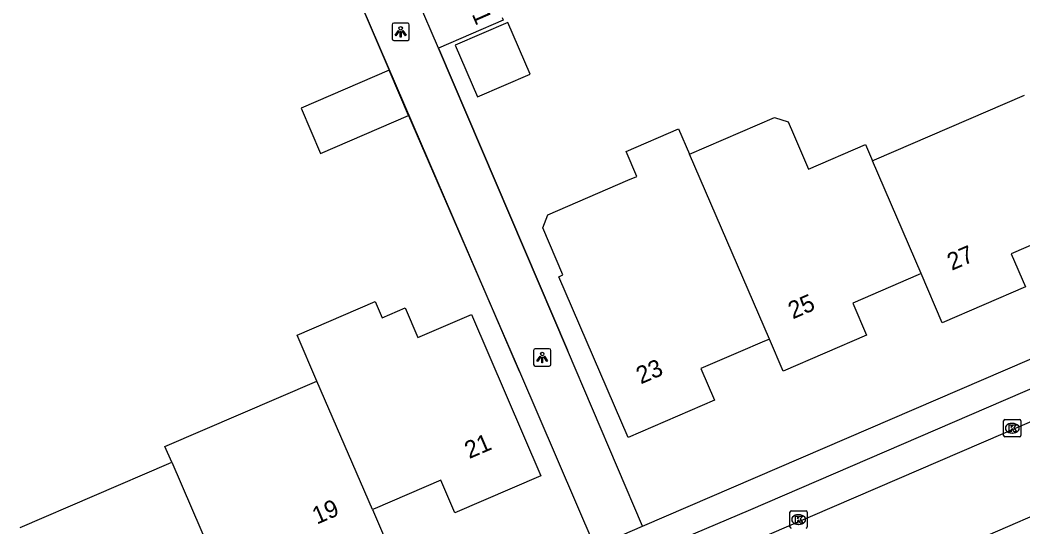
# Model space of a CAD drawing. Extents: x 157767 to 159171, y 387842 to 389425.
# Drawn here: x 158190.7 to 158248.5, y 388683 to 388712.2 of the extents above; entities that cross this region are included whole.
import ezdxf

# ---------------------------------------------------------------- set-up
doc = ezdxf.new("R2010")
doc.units = 0
for name, color, linetype in [('IMGEO_Kolk', 7, 'Continuous'), ('IMGEO_Lichtpunt', 7, 'Continuous'), ('IMGEO_Muur', 7, 'Continuous'), ('IMGEO_Pand', 7, 'Continuous'), ('IMGEO_Pand_nummerreeks', 7, 'Continuous'), ('IMGEO_Rijbaan_lokaal_open', 7, 'Continuous'), ('IMGEO_Voetpad_open', 7, 'Continuous')]:
    doc.layers.add(name, color=color, linetype=linetype)

msp = doc.modelspace()

# ---------------------------------------------------------------- linework, layer by layer
at = {"layer": 'IMGEO_Kolk'}
for p, q in [((158247.391, 388688.278), (158247.391, 388689.13)), ((158247.466, 388689.204), (158248.318, 388689.204)), ((158247.879, 388688.984), (158247.904, 388688.984)), ((158248.392, 388689.13), (158248.392, 388688.278)), ((158248.318, 388688.204), (158247.466, 388688.204)), ((158247.902, 388688.424), (158247.877, 388688.424)), ((158235.076, 388683.017), (158235.076, 388683.869)), ((158235.151, 388683.943), (158236.003, 388683.943)), ((158235.564, 388683.723), (158235.589, 388683.723)), ((158236.077, 388683.869), (158236.077, 388683.017)), ((158235.587, 388683.163), (158235.562, 388683.163))]:
    msp.add_line(p, q, dxfattribs=at)
for points in [[(158247.391, 388688.278), (158247.391, 388689.13)], [(158247.466, 388689.204), (158248.318, 388689.204)], [(158247.712, 388688.904), (158247.835, 388688.904), (158247.835, 388688.753), (158247.965, 388688.904), (158248.129, 388688.904), (158247.983, 388688.753), (158248.136, 388688.504), (158247.984, 388688.504), (158247.899, 388688.668), (158247.835, 388688.601), (158247.835, 388688.504), (158247.712, 388688.504), (158247.712, 388688.904)], [(158248.392, 388689.13), (158248.392, 388688.278)], [(158248.318, 388688.204), (158247.466, 388688.204)], [(158235.076, 388683.017), (158235.076, 388683.869)], [(158235.151, 388683.943), (158236.003, 388683.943)], [(158235.397, 388683.643), (158235.52, 388683.643), (158235.52, 388683.492), (158235.65, 388683.643), (158235.814, 388683.643), (158235.668, 388683.492), (158235.821, 388683.243), (158235.669, 388683.243), (158235.584, 388683.407), (158235.52, 388683.34), (158235.52, 388683.243), (158235.397, 388683.243), (158235.397, 388683.643)], [(158236.077, 388683.869), (158236.077, 388683.017)]]:
    msp.add_lwpolyline(points, dxfattribs=at)
for centre, start, end in [((158247.468, 388689.128), 91.55205, 178.44795), ((158247.468, 388689.128), 91.55205, 178.44795), ((158248.316, 388689.128), 1.55205, 88.44795), ((158248.316, 388689.128), 1.55205, 88.44795), ((158247.468, 388688.28), 181.55205, 268.44795), ((158247.468, 388688.28), 181.55205, 268.44795), ((158248.316, 388688.28), 271.55205, 358.44795), ((158248.316, 388688.28), 271.55205, 358.44795), ((158235.153, 388683.867), 91.55205, 178.44795), ((158235.153, 388683.867), 91.55205, 178.44795), ((158236.001, 388683.867), 1.55205, 88.44795), ((158236.001, 388683.867), 1.55205, 88.44795), ((158235.153, 388683.019), 181.55205, 268.44795), ((158235.153, 388683.019), 181.55205, 268.44795), ((158236.001, 388683.019), 271.55205, 358.44795), ((158236.001, 388683.019), 271.55205, 358.44795)]:
    msp.add_arc(centre, 0.0765, start, end, dxfattribs=at)
for centre, major_axis, ratio, start_param, end_param in [((158247.878, 388688.704), (-0.387, 0.002), 0.722429, 4.712389, 7.853982), ((158247.903, 388688.704), (-0.39, 0.002), 0.717154, 1.570796, 4.712389), ((158235.563, 388683.443), (-0.387, 0.002), 0.722429, 4.712389, 7.853982), ((158235.588, 388683.443), (-0.39, 0.002), 0.717154, 1.570796, 4.712389)]:
    msp.add_ellipse(centre, major_axis=major_axis, ratio=ratio, start_param=start_param, end_param=end_param, dxfattribs=at)
at = {"layer": 'IMGEO_Lichtpunt'}
for p, q in [((158212.142, 388711.942), (158212.142, 388711.135)), ((158212.142, 388711.942), (158212.142, 388711.135)), ((158213.044, 388712.037), (158212.236, 388712.037)), ((158213.044, 388712.037), (158212.236, 388712.037)), ((158213.138, 388711.135), (158213.138, 388711.942)), ((158213.138, 388711.135), (158213.138, 388711.942)), ((158212.236, 388711.041), (158213.044, 388711.041)), ((158212.236, 388711.041), (158213.044, 388711.041)), ((158220.3, 388693.182), (158220.3, 388692.375)), ((158220.3, 388693.182), (158220.3, 388692.375)), ((158221.202, 388693.277), (158220.394, 388693.277)), ((158221.202, 388693.277), (158220.394, 388693.277)), ((158221.296, 388692.375), (158221.296, 388693.182)), ((158221.296, 388692.375), (158221.296, 388693.182)), ((158220.394, 388692.281), (158221.202, 388692.281)), ((158220.394, 388692.281), (158221.202, 388692.281))]:
    msp.add_line(p, q, dxfattribs=at)
for points in [[(158212.516, 388711.606), (158212.555, 388711.578), (158212.367, 388711.316), (158212.329, 388711.343), (158212.516, 388711.606)], [(158212.618, 388711.558), (158212.665, 388711.558), (158212.665, 388711.236), (158212.618, 388711.236), (158212.618, 388711.558)], [(158212.728, 388711.578), (158212.766, 388711.605), (158212.953, 388711.343), (158212.914, 388711.315), (158212.728, 388711.578)], [(158220.674, 388692.846), (158220.713, 388692.818), (158220.525, 388692.556), (158220.487, 388692.583), (158220.674, 388692.846)], [(158220.776, 388692.798), (158220.823, 388692.798), (158220.823, 388692.476), (158220.776, 388692.476), (158220.776, 388692.798)], [(158220.886, 388692.818), (158220.924, 388692.845), (158221.111, 388692.583), (158221.072, 388692.555), (158220.886, 388692.818)]]:
    msp.add_lwpolyline(points, dxfattribs=at)
for centre in [(158212.641, 388711.74), (158220.799, 388692.98)]:
    msp.add_circle(centre, 0.0994, dxfattribs=at)
for centre, start, end in [((158212.236, 388711.942), 90, 180), ((158212.236, 388711.942), 90, 180), ((158213.044, 388711.942), 0, 90), ((158213.044, 388711.942), 0, 90), ((158212.236, 388711.135), 180, 270), ((158212.236, 388711.135), 180, 270), ((158213.044, 388711.135), 270, 0), ((158213.044, 388711.135), 270, 360), ((158220.394, 388693.182), 90, 180), ((158220.394, 388693.182), 90, 180), ((158221.202, 388693.182), 0, 90), ((158221.202, 388693.182), 0, 90), ((158220.394, 388692.375), 180, 270), ((158220.394, 388692.375), 180, 270), ((158221.202, 388692.375), 270, 0), ((158221.202, 388692.375), 270, 360)]:
    msp.add_arc(centre, 0.0946, start, end, dxfattribs=at)
at = {"layer": 'IMGEO_Muur'}
for points in [[(158219.492, 388691.965), (158208.082, 388718.445), (158205.742, 388723.876)], [(158214.816, 388710.595), (158222.246, 388693.191)]]:
    msp.add_lwpolyline(points, dxfattribs=at)
at = {"layer": 'IMGEO_Pand'}
for points in [[(158214.816, 388710.595), (158213.602, 388713.414)], [(158218.48, 388712.357), (158218.547, 388712.202), (158214.816, 388710.595)], [(158215.79, 388710.767), (158217.072, 388707.789), (158220.106, 388709.096), (158218.824, 388712.074), (158215.79, 388710.767)], [(158211.972, 388709.33), (158206.896, 388707.144), (158208.021, 388704.53), (158213.098, 388706.716)], [(158213.098, 388706.716), (158211.972, 388709.33)], [(158239.84, 388704.111), (158239.947, 388704.157), (158248.597, 388707.882)], [(158229.293, 388704.49), (158234.184, 388706.595), (158234.98, 388706.355), (158235.287, 388705.642), (158236.152, 388703.634), (158239.437, 388705.049), (158239.84, 388704.111)], [(158233.895, 388693.842), (158233.481, 388693.663), (158232.221, 388693.121), (158229.942, 388692.139), (158230.729, 388690.311), (158225.746, 388688.165), (158221.755, 388697.433), (158221.994, 388697.536), (158220.824, 388700.255), (158221.123, 388701.005), (158225.725, 388702.986), (158226.249, 388703.211), (158225.629, 388704.652), (158228.644, 388705.95), (158229.293, 388704.49)], [(158233.895, 388693.842), (158229.293, 388704.49)], [(158242.631, 388697.609), (158239.84, 388704.111)], [(158251.79, 388700.46), (158247.825, 388698.752), (158248.644, 388696.85), (158243.844, 388694.783), (158242.631, 388697.609)], [(158242.631, 388697.609), (158242.462, 388697.536), (158238.694, 388695.913), (158239.493, 388694.059), (158234.695, 388691.992), (158233.895, 388693.842)], [(158207.814, 388691.423), (158206.671, 388694.073), (158211.164, 388696.012), (158211.575, 388695.06), (158212.904, 388695.633), (158213.637, 388693.932), (158216.719, 388695.259), (158220.723, 388685.962), (158215.765, 388683.826), (158214.953, 388685.71), (158211.176, 388684.083), (158211.011, 388684.012)], [(158199.444, 388686.74), (158199.051, 388687.649), (158207.814, 388691.423)], [(158211.011, 388684.012), (158207.814, 388691.423)], [(158190.702, 388682.975), (158199.284, 388686.671), (158199.444, 388686.74)], [(158199.444, 388686.74), (158202.255, 388680.24)], [(158211.011, 388684.012), (158211.822, 388682.131), (158206.977, 388680.044), (158206.167, 388681.924), (158202.402, 388680.303), (158202.255, 388680.24)]]:
    msp.add_lwpolyline(points, dxfattribs=at)
at = {"layer": 'IMGEO_Rijbaan_lokaal_open'}
for points in [[(158229.383, 388680.571), (158233.906, 388682.603), (158267.072, 388696.894), (158267.966, 388697.279)], [(158255.291, 388686.339), (158244.298, 388681.584)]]:
    msp.add_lwpolyline(points, dxfattribs=at)
at = {"layer": 'IMGEO_Voetpad_open'}
for points in [[(158208.082, 388718.445), (158211.972, 388709.33)], [(158226.572, 388683.059), (158265.791, 388699.949), (158281.335, 388706.644), (158293.914, 388712.06)], [(158226.572, 388683.059), (158222.246, 388693.191), (158214.816, 388710.595)], [(158291.521, 388707.835), (158291.008, 388709.09), (158232.675, 388683.946), (158229.007, 388682.388), (158229.575, 388681.033)], [(158213.098, 388706.716), (158219.492, 388691.965), (158223.84, 388681.871)], [(158223.84, 388681.871), (158226.572, 388683.059)]]:
    msp.add_lwpolyline(points, dxfattribs=at)

# ---------------------------------------------------------------- texts
at = {"layer": 'IMGEO_Pand_nummerreeks'}
for s, rotation, p in [('21/N01', 293.44806, (158215.306, 388715.829)), ('27', 23.29073, (158244.405, 388697.769)), ('25', 23.30792, (158235.24, 388694.97)), ('23', 23.30219, (158226.481, 388691.225)), ('21', 23.30792, (158216.593, 388686.925)), ('19', 23.30792, (158207.81, 388683.146))]:
    msp.add_text(s, height=1, rotation=rotation, dxfattribs=at).set_placement(p)

doc.saveas('drawing.dxf')
